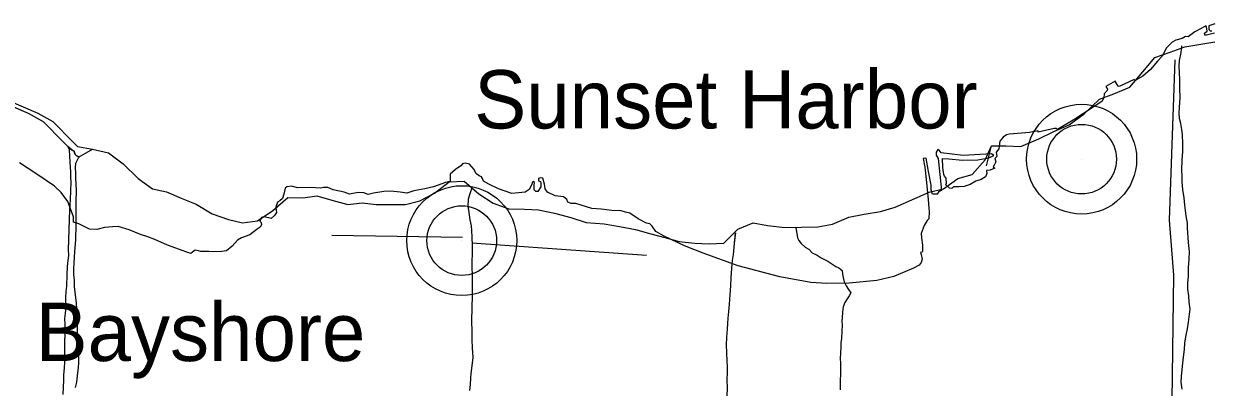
# Model space of a CAD drawing. Extents: x 0 to 34, y 0 to 22.
# Drawn here: x 3.462 to 4.264, y 15.022 to 15.268 of the extents above; entities that cross this region are included whole.
import ezdxf

# ---------------------------------------------------------------- set-up
doc = ezdxf.new("R2010")
doc.units = 0
for name, color, linetype in [('GM_X_Corporation', 7, 'Continuous'), ('GM_X_Major_Lake', 7, 'Continuous'), ('GM_X_Minor_River', 7, 'Continuous'), ('GM_X_Township_Road', 7, 'Continuous'), ('GM_X_Unincorporated', 7, 'Continuous'), ('GM_X_Unincorporated_Location', 7, 'Continuous'), ('GM_X_Unincorporated_Text', 7, 'Continuous')]:
    doc.layers.add(name, color=color, linetype=linetype)

msp = doc.modelspace()

# ---------------------------------------------------------------- linework, layer by layer
at = {"layer": 'GM_X_Corporation'}
for points in [[(4.26677, 15.262), (4.26154, 15.26063), (4.26034, 15.26054), (4.26, 15.262), (4.26197, 15.2632), (4.26154, 15.2662), (4.26103, 15.2668), (4.25794, 15.26517), (4.25366, 15.26294), (4.24903, 15.25951), (4.24723, 15.25977), (4.24492, 15.25831), (4.24063, 15.2572), (4.23831, 15.25574), (4.23437, 15.25206), (4.23137, 15.24631), (4.22829, 15.24305), (4.22357, 15.2374), (4.21832, 15.23276), (4.21316, 15.22976), (4.2126, 15.23046), (4.20246, 15.22589), (4.20163, 15.22608), (4.19974, 15.22943), (4.1934, 15.22583), (4.1946, 15.22394), (4.19434, 15.22308), (4.1922, 15.22094), (4.19203, 15.21803), (4.19057, 15.21571), (4.17232, 15.20371), (4.16075, 15.19677), (4.16006, 15.19728), (4.15852, 15.19746), (4.15346, 15.19617), (4.14754, 15.19497), (4.14763, 15.19574), (4.14172, 15.19463), (4.12817, 15.19343), (4.12612, 15.19317), (4.12397, 15.19146), (4.12166, 15.18871), (4.12098, 15.18357), (4.11926, 15.18134), (4.11977, 15.17843), (4.1184, 15.17697), (4.119, 15.17474), (4.11814, 15.17303), (4.11712, 15.1714), (4.11823, 15.17046), (4.11506, 15.16917), (4.11275, 15.16883), (4.113, 15.16686), (4.11189, 15.16463), (4.10915, 15.16283), (4.10546, 15.16171), (4.10169, 15.15949), (4.09766, 15.15803), (4.09423, 15.15786), (4.09038, 15.15786), (4.08917, 15.15674), (4.08755, 15.15691), (4.08515, 15.15914), (4.08558, 15.16026), (4.0854, 15.16368), (4.08437, 15.16514), (4.08377, 15.16626), (4.08309, 15.17106), (4.08283, 15.17697), (4.0872, 15.17688), (4.09637, 15.17586), (4.10675, 15.1762), (4.1142, 15.17757), (4.11763, 15.17903), (4.116, 15.18014), (4.09689, 15.17911), (4.08197, 15.18083), (4.08069, 15.18263), (4.07975, 15.18314), (4.07854, 15.18134), (4.07854, 15.17937), (4.07992, 15.17714), (4.08215, 15.15546), (4.08052, 15.15477), (4.07923, 15.15288), (4.07606, 15.1528), (4.07529, 15.15571), (4.0752, 15.15889), (4.0734, 15.16823), (4.07177, 15.17731), (4.06989, 15.17706), (4.071, 15.17123), (4.07203, 15.16086), (4.07315, 15.14929), (4.07357, 15.14337), (4.07383, 15.14106), (4.07357, 15.13617), (4.07263, 15.13514), (4.07058, 15.13163), (4.06843, 15.12623), (4.06869, 15.12323), (4.06938, 15.11834), (4.06929, 15.11406), (4.06886, 15.11354), (4.068, 15.11337), (4.0686, 15.11209), (4.06912, 15.10883), (4.06843, 15.10651), (4.06715, 15.1048), (4.06329, 15.10283), (4.04992, 15.09717), (4.0386, 15.09452), (4.01975, 15.09254), (4.00466, 15.09229), (3.99378, 15.09306), (3.97286, 15.09691), (3.94466, 15.10429), (3.92109, 15.11303), (3.9085, 15.1178), (3.90421, 15.11989), (3.89461, 15.12434), (3.88895, 15.1276), (3.88655, 15.13129), (3.88492, 15.13283), (3.88278, 15.13326), (3.87703, 15.13617), (3.87155, 15.13994), (3.86864, 15.14063), (3.86555, 15.14166), (3.85929, 15.14183), (3.85218, 15.14268), (3.84575, 15.14311), (3.83487, 15.14646), (3.83178, 15.14646), (3.82964, 15.14757), (3.82895, 15.14929), (3.82664, 15.15109), (3.82089, 15.15177), (3.81575, 15.15417), (3.81429, 15.1564), (3.81387, 15.15974), (3.81258, 15.16377), (3.81112, 15.16403), (3.80975, 15.16343), (3.80967, 15.16188), (3.81112, 15.16154), (3.81138, 15.16034), (3.81129, 15.15777), (3.80924, 15.15469), (3.80795, 15.15469), (3.80675, 15.15571), (3.80675, 15.15889), (3.80692, 15.16086), (3.80615, 15.16137), (3.80564, 15.16103), (3.80495, 15.15889), (3.80341, 15.15614), (3.80066, 15.15417), (3.79166, 15.15331), (3.78258, 15.15657), (3.77606, 15.15966), (3.77255, 15.1618), (3.77195, 15.16343), (3.77109, 15.16454), (3.76998, 15.16506), (3.76758, 15.16668), (3.76629, 15.16969), (3.76304, 15.17311), (3.76021, 15.1738), (3.75824, 15.17346), (3.75712, 15.172), (3.75361, 15.1696), (3.75172, 15.16806), (3.75001, 15.16643), (3.74992, 15.16326), (3.75001, 15.16154), (3.74692, 15.16069), (3.7387, 15.15777), (3.73278, 15.15657), (3.72532, 15.15512), (3.72078, 15.15348), (3.71624, 15.15426), (3.70981, 15.15494), (3.70518, 15.15477), (3.69815, 15.15366), (3.69447, 15.15271), (3.69164, 15.15374), (3.68787, 15.15409), (3.68195, 15.1528), (3.67835, 15.15426), (3.67089, 15.15589), (3.66729, 15.15734), (3.66438, 15.15751), (3.66249, 15.15691), (3.6553, 15.15743), (3.64681, 15.15717), (3.64287, 15.15837), (3.63944, 15.15794), (3.63833, 15.15691), (3.63755, 15.1528), (3.63669, 15.14997), (3.63481, 15.14843), (3.6331, 15.1474), (3.63198, 15.14414), (3.6325, 15.14046), (3.63112, 15.1384), (3.62896, 15.1363), (3.6241, 15.13746), (3.62247, 15.13711), (3.62124, 15.13468), (3.62221, 15.1336), (3.62247, 15.13223), (3.62144, 15.13052), (3.61955, 15.12914), (3.61441, 15.12529), (3.60875, 15.12331), (3.60618, 15.12177), (3.6025, 15.11757), (3.59873, 15.11457), (3.59564, 15.11397), (3.58981, 15.11389), (3.58681, 15.11414), (3.58132, 15.11414), (3.57987, 15.11457), (3.57747, 15.11492), (3.57567, 15.11371), (3.57455, 15.11277), (3.57198, 15.11354), (3.55878, 15.11843), (3.5503, 15.12228), (3.54541, 15.12409), (3.54061, 15.12554), (3.53281, 15.12871), (3.52544, 15.13103), (3.52158, 15.13086), (3.51627, 15.13026), (3.51095, 15.12897), (3.50615, 15.12914), (3.49878, 15.13274), (3.49527, 15.13386), (3.49518, 15.13754), (3.49133, 15.148), (3.48695, 15.154), (3.48233, 15.15828), (3.47041, 15.16634), (3.45867, 15.17414)], [(4.26677, 15.262), (4.26154, 15.26063), (4.26034, 15.26054), (4.26, 15.262), (4.26197, 15.2632), (4.26154, 15.2662), (4.26103, 15.2668), (4.25794, 15.26517), (4.25366, 15.26294), (4.24903, 15.25951), (4.24723, 15.25977), (4.24492, 15.25831), (4.24063, 15.2572), (4.23831, 15.25574), (4.23437, 15.25206), (4.23137, 15.24631), (4.22829, 15.24305), (4.22357, 15.2374), (4.21832, 15.23276), (4.21316, 15.22976), (4.2126, 15.23046), (4.20246, 15.22589), (4.20163, 15.22608), (4.19974, 15.22943), (4.1934, 15.22583), (4.1946, 15.22394), (4.19434, 15.22308), (4.1922, 15.22094), (4.19203, 15.21803), (4.19057, 15.21571), (4.17232, 15.20371), (4.16075, 15.19677), (4.16006, 15.19728), (4.15852, 15.19746), (4.15346, 15.19617), (4.14754, 15.19497), (4.14763, 15.19574), (4.14172, 15.19463), (4.12817, 15.19343), (4.12612, 15.19317), (4.12397, 15.19146), (4.12166, 15.18871), (4.12098, 15.18357), (4.11926, 15.18134), (4.11977, 15.17843), (4.1184, 15.17697), (4.119, 15.17474), (4.11814, 15.17303), (4.11712, 15.1714), (4.11823, 15.17046), (4.11506, 15.16917), (4.11275, 15.16883), (4.113, 15.16686), (4.11189, 15.16463), (4.10915, 15.16283), (4.10546, 15.16171), (4.10169, 15.15949), (4.09766, 15.15803), (4.09423, 15.15786), (4.09038, 15.15786), (4.08917, 15.15674), (4.08755, 15.15691), (4.08515, 15.15914), (4.08558, 15.16026), (4.0854, 15.16368), (4.08437, 15.16514), (4.08377, 15.16626), (4.08309, 15.17106), (4.08283, 15.17697), (4.0872, 15.17688), (4.09637, 15.17586), (4.10675, 15.1762), (4.1142, 15.17757), (4.11763, 15.17903), (4.116, 15.18014), (4.09689, 15.17911), (4.08197, 15.18083), (4.08069, 15.18263), (4.07975, 15.18314), (4.07854, 15.18134), (4.07854, 15.17937), (4.07992, 15.17714), (4.08215, 15.15546), (4.08052, 15.15477), (4.07923, 15.15288), (4.07606, 15.1528), (4.07529, 15.15571), (4.0752, 15.15889), (4.0734, 15.16823), (4.07177, 15.17731), (4.06989, 15.17706), (4.071, 15.17123), (4.07203, 15.16086), (4.07315, 15.14929), (4.07357, 15.14337), (4.07383, 15.14106), (4.07357, 15.13617), (4.07263, 15.13514), (4.07058, 15.13163), (4.06843, 15.12623), (4.06869, 15.12323), (4.06938, 15.11834), (4.06929, 15.11406), (4.06886, 15.11354), (4.068, 15.11337), (4.0686, 15.11209), (4.06912, 15.10883), (4.06843, 15.10651), (4.06715, 15.1048), (4.06329, 15.10283), (4.04992, 15.09717), (4.0386, 15.09452), (4.01975, 15.09254), (4.00466, 15.09229), (3.99378, 15.09306), (3.97286, 15.09691), (3.94466, 15.10429), (3.92109, 15.11303), (3.9085, 15.1178), (3.90421, 15.11989), (3.89461, 15.12434), (3.88895, 15.1276), (3.88655, 15.13129), (3.88492, 15.13283), (3.88278, 15.13326), (3.87703, 15.13617), (3.87155, 15.13994), (3.86864, 15.14063), (3.86555, 15.14166), (3.85929, 15.14183), (3.85218, 15.14268), (3.84575, 15.14311), (3.83487, 15.14646), (3.83178, 15.14646), (3.82964, 15.14757), (3.82895, 15.14929), (3.82664, 15.15109), (3.82089, 15.15177), (3.81575, 15.15417), (3.81429, 15.1564), (3.81387, 15.15974), (3.81258, 15.16377), (3.81112, 15.16403), (3.80975, 15.16343), (3.80967, 15.16188), (3.81112, 15.16154), (3.81138, 15.16034), (3.81129, 15.15777), (3.80924, 15.15469), (3.80795, 15.15469), (3.80675, 15.15571), (3.80675, 15.15889), (3.80692, 15.16086), (3.80615, 15.16137), (3.80564, 15.16103), (3.80495, 15.15889), (3.80341, 15.15614), (3.80066, 15.15417), (3.79166, 15.15331), (3.78258, 15.15657), (3.77606, 15.15966), (3.77255, 15.1618), (3.77195, 15.16343), (3.77109, 15.16454), (3.76998, 15.16506), (3.76758, 15.16668), (3.76629, 15.16969), (3.76304, 15.17311), (3.76021, 15.1738), (3.75824, 15.17346), (3.75712, 15.172), (3.75361, 15.1696), (3.75172, 15.16806), (3.75001, 15.16643), (3.74992, 15.16326), (3.75001, 15.16154), (3.74692, 15.16069), (3.7387, 15.15777), (3.73278, 15.15657), (3.72532, 15.15512), (3.72078, 15.15348), (3.71624, 15.15426), (3.70981, 15.15494), (3.70518, 15.15477), (3.69815, 15.15366), (3.69447, 15.15271), (3.69164, 15.15374), (3.68787, 15.15409), (3.68195, 15.1528), (3.67835, 15.15426), (3.67089, 15.15589), (3.66729, 15.15734), (3.66438, 15.15751), (3.66249, 15.15691), (3.6553, 15.15743), (3.64681, 15.15717), (3.64287, 15.15837), (3.63944, 15.15794), (3.63833, 15.15691), (3.63755, 15.1528), (3.63669, 15.14997), (3.63481, 15.14843), (3.6331, 15.1474), (3.63198, 15.14414), (3.6325, 15.14046), (3.63112, 15.1384), (3.62896, 15.1363), (3.6241, 15.13746), (3.62247, 15.13711), (3.62124, 15.13468), (3.62221, 15.1336), (3.62247, 15.13223), (3.62144, 15.13052), (3.61955, 15.12914), (3.61441, 15.12529), (3.60875, 15.12331), (3.60618, 15.12177), (3.6025, 15.11757), (3.59873, 15.11457), (3.59564, 15.11397), (3.58981, 15.11389), (3.58681, 15.11414), (3.58132, 15.11414), (3.57987, 15.11457), (3.57747, 15.11492), (3.57567, 15.11371), (3.57455, 15.11277), (3.57198, 15.11354), (3.55878, 15.11843), (3.5503, 15.12228), (3.54541, 15.12409), (3.54061, 15.12554), (3.53281, 15.12871), (3.52544, 15.13103), (3.52158, 15.13086), (3.51627, 15.13026), (3.51095, 15.12897), (3.50615, 15.12914), (3.49878, 15.13274), (3.49527, 15.13386), (3.49518, 15.13754), (3.49133, 15.148), (3.48695, 15.154), (3.48233, 15.15828), (3.47041, 15.16634), (3.45867, 15.17414)], [(4.2672, 15.26834), (4.26309, 15.26688), (4.263, 15.26448), (4.26386, 15.26354), (4.26497, 15.26354)], [(4.2672, 15.26834), (4.26309, 15.26688), (4.263, 15.26448), (4.26386, 15.26354), (4.26497, 15.26354)]]:
    msp.add_lwpolyline(points, dxfattribs=at)
at = {"layer": 'GM_X_Major_Lake'}
for points in [[(3.36062, 15.25814), (3.37105, 15.25226), (3.38109, 15.25036), (3.39209, 15.24599), (3.40308, 15.24011), (3.41294, 15.23441), (3.42412, 15.22967), (3.4353, 15.22245), (3.44478, 15.21638), (3.45464, 15.21201), (3.46468, 15.20784), (3.47473, 15.20214), (3.48857, 15.18809), (3.49141, 15.18516)], [(3.36714, 15.25814), (3.37756, 15.25226), (3.38761, 15.25036), (3.3986, 15.24599), (3.40959, 15.24011), (3.41945, 15.23441), (3.43063, 15.22967), (3.44181, 15.22245), (3.45129, 15.21638), (3.46115, 15.21201), (3.47119, 15.20784), (3.48124, 15.20214), (3.49508, 15.18809), (3.49792, 15.18516)], [(3.49792, 15.18516), (3.50809, 15.18335), (3.51889, 15.18088), (3.52894, 15.17348), (3.53898, 15.16341), (3.54865, 15.15658), (3.55813, 15.15449), (3.56817, 15.15013), (3.57822, 15.14614), (3.58902, 15.13968), (3.60002, 15.1357), (3.60949, 15.13342), (3.61973, 15.13494), (3.62996, 15.14178), (3.64019, 15.15071), (3.65024, 15.15033), (3.6599, 15.15185), (3.66995, 15.14881), (3.68075, 15.14578), (3.69042, 15.14692), (3.69989, 15.14578), (3.71032, 15.14578), (3.71979, 15.14597), (3.72946, 15.14844), (3.73931, 15.15357), (3.74935, 15.16117), (3.7594, 15.16174), (3.76945, 15.15301), (3.77911, 15.14674), (3.78973, 15.14295), (3.80015, 15.14276), (3.80963, 15.14219), (3.82043, 15.13991), (3.83161, 15.13706), (3.84204, 15.13365), (3.85417, 15.13289), (3.86459, 15.13099), (3.8752, 15.12891), (3.88563, 15.12606), (3.8951, 15.12359), (3.90477, 15.12093), (3.9152, 15.1198), (3.92505, 15.11923), (3.93509, 15.11961), (3.94457, 15.12929), (3.9548, 15.13347), (3.96466, 15.13158), (3.9766, 15.13025), (3.98759, 15.13044), (3.99858, 15.13082), (4.00863, 15.13253), (4.01962, 15.13728), (4.03004, 15.13937), (4.04104, 15.14108), (4.05089, 15.14412), (4.06416, 15.15001), (4.07382, 15.15419), (4.08349, 15.15647), (4.09334, 15.1635), (4.10301, 15.16616), (4.11172, 15.17603), (4.11608, 15.18553), (4.12575, 15.18572), (4.13579, 15.18515), (4.14811, 15.19047), (4.15815, 15.19541), (4.16858, 15.19978), (4.17881, 15.20737), (4.18904, 15.21725), (4.1989, 15.22086), (4.2097, 15.22542), (4.21842, 15.23568), (4.22656, 15.24555), (4.2368, 15.24916), (4.24684, 15.25277), (4.25632, 15.25429), (4.26712, 15.256)], [(3.49912, 15.17818), (3.50809, 15.18335), (3.51889, 15.18088), (3.52894, 15.17348), (3.53898, 15.16341), (3.54865, 15.15658), (3.55813, 15.15449), (3.56817, 15.15013), (3.57822, 15.14614), (3.58902, 15.13968), (3.60002, 15.1357), (3.60949, 15.13342), (3.61973, 15.13494), (3.62996, 15.14178), (3.64019, 15.15071), (3.65024, 15.15033), (3.6599, 15.15185), (3.66995, 15.14881), (3.68075, 15.14578), (3.69042, 15.14692), (3.69989, 15.14578), (3.71032, 15.14578), (3.71979, 15.14597), (3.72946, 15.14844), (3.73931, 15.15357), (3.74935, 15.16117), (3.7594, 15.16174), (3.76945, 15.15301), (3.77911, 15.14674), (3.78973, 15.14295), (3.80015, 15.14276), (3.80963, 15.14219), (3.82043, 15.13991), (3.83161, 15.13706), (3.84204, 15.13365), (3.85417, 15.13289), (3.86459, 15.13099), (3.8752, 15.12891), (3.88563, 15.12606), (3.8951, 15.12359), (3.90477, 15.12093), (3.9152, 15.1198), (3.92505, 15.11923), (3.93509, 15.11961), (3.94457, 15.12929), (3.9548, 15.13347), (3.96466, 15.13158), (3.9766, 15.13025), (3.98759, 15.13044), (3.99858, 15.13082), (4.00863, 15.13253), (4.01962, 15.13728), (4.03004, 15.13937), (4.04104, 15.14108), (4.05089, 15.14412), (4.06416, 15.15001), (4.07382, 15.15419), (4.08349, 15.15647), (4.09334, 15.1635), (4.10301, 15.16616), (4.11172, 15.17603), (4.11608, 15.18553), (4.12575, 15.18572), (4.13579, 15.18515), (4.14811, 15.19047), (4.15815, 15.19541), (4.16858, 15.19978), (4.17881, 15.20737), (4.18904, 15.21725), (4.1989, 15.22086), (4.2097, 15.22542), (4.21842, 15.23568), (4.22656, 15.24555), (4.2368, 15.24916), (4.24684, 15.25277), (4.25632, 15.25429), (4.26712, 15.256)], [(4.11275, 15.17205), (4.11608, 15.18553), (4.12575, 15.18572), (4.13579, 15.18515), (4.14811, 15.19047), (4.15815, 15.19541), (4.16858, 15.19978), (4.17881, 15.20737), (4.18904, 15.21725), (4.1989, 15.22086), (4.2097, 15.22542), (4.21842, 15.23568), (4.22656, 15.24555), (4.2368, 15.24916), (4.24684, 15.25277), (4.25632, 15.25429), (4.26712, 15.256)], [(3.49141, 15.18516), (3.4944, 15.18276), (3.49567, 15.18195), (3.49594, 15.18087), (3.49642, 15.17973), (3.49701, 15.17917), (3.49787, 15.17861), (3.49912, 15.17818)]]:
    msp.add_lwpolyline(points, dxfattribs=at)
at = {"layer": 'GM_X_Minor_River'}
for p in [(3.76464, 15.11999), (3.88273, 15.11166)]:
    msp.add_line(p, (3.88273, 15.11166), dxfattribs=at)
for points in [[(4.24495, 15.02071), (4.24433, 15.02567), (4.24444, 15.02946), (4.24521, 15.03647), (4.2457, 15.04045), (4.24667, 15.04783), (4.24679, 15.052), (4.24748, 15.05616), (4.24858, 15.06164), (4.24928, 15.06618), (4.25001, 15.07167), (4.2503, 15.07508), (4.24967, 15.07985), (4.24941, 15.08403), (4.24878, 15.08861), (4.2489, 15.09279), (4.24922, 15.09715), (4.24939, 15.10322), (4.24973, 15.10872), (4.24989, 15.11404), (4.2493, 15.12013), (4.24863, 15.13003), (4.24854, 15.13326), (4.24773, 15.13823), (4.2468, 15.14547), (4.24637, 15.15043), (4.24539, 15.15615), (4.24497, 15.16129), (4.24489, 15.16529), (4.24481, 15.16909), (4.24501, 15.17611), (4.24536, 15.1818), (4.24551, 15.18693), (4.24512, 15.19321), (4.24484, 15.19663), (4.2442, 15.20083), (4.24315, 15.20409), (4.24308, 15.20808), (4.24317, 15.2115), (4.24355, 15.21814), (4.24336, 15.22479), (4.24333, 15.2303), (4.24309, 15.23525), (4.24303, 15.23962), (4.24313, 15.24342), (4.24424, 15.2489), (4.24475, 15.25344)], [(3.49141, 15.18516), (3.4923, 15.18322), (3.49255, 15.17866), (3.49282, 15.17466), (3.49291, 15.17124), (3.4932, 15.168), (3.49329, 15.16439), (3.49338, 15.16097), (3.49304, 15.1492), (3.49275, 15.1456), (3.49246, 15.14218), (3.4917, 15.11542), (3.49178, 15.11143), (3.49149, 15.10802), (3.49099, 15.10385), (3.49064, 15.09835), (3.49042, 15.09057), (3.49013, 15.08697), (3.48982, 15.0828), (3.48991, 15.07937), (3.49001, 15.07614), (3.48952, 15.07236), (3.48923, 15.06857), (3.4893, 15.06457), (3.48957, 15.06077), (3.48947, 15.05716), (3.48918, 15.05375), (3.48909, 15.05033), (3.48916, 15.04615), (3.48925, 15.04273), (3.48914, 15.03893), (3.48885, 15.03533), (3.48852, 15.0304), (3.48842, 15.02698), (3.48814, 15.0173)], [(3.49912, 15.17818), (3.49787, 15.17861), (3.49701, 15.17917), (3.49642, 15.17973), (3.49594, 15.18087), (3.49567, 15.18195), (3.4944, 15.18276), (3.49141, 15.18516)], [(3.49663, 15.022), (3.49749, 15.02558), (3.49799, 15.02975), (3.49853, 15.03543), (3.49882, 15.03865), (3.49877, 15.04378), (3.49852, 15.04835), (3.49842, 15.05158), (3.49814, 15.05482), (3.49789, 15.05958), (3.49799, 15.06299), (3.49773, 15.06718), (3.49769, 15.07231), (3.4974, 15.07555), (3.49731, 15.07916), (3.49685, 15.08297), (3.49637, 15.08622), (3.49592, 15.09041), (3.49585, 15.09459), (3.49558, 15.0984), (3.49551, 15.10258), (3.49561, 15.106), (3.49592, 15.11017), (3.49621, 15.11377), (3.49683, 15.12211), (3.49711, 15.13198), (3.49704, 15.13616), (3.49714, 15.13996), (3.49705, 15.14338), (3.49697, 15.14699), (3.49722, 15.15592), (3.49712, 15.15915), (3.49688, 15.1639), (3.49679, 15.16733), (3.49669, 15.17075), (3.49679, 15.17398), (3.49852, 15.17757), (3.49912, 15.17818)], [(3.76469, 15.157), (3.7635, 15.15374), (3.76225, 15.14959), (3.76192, 15.14466), (3.76256, 15.14047), (3.76336, 15.1355), (3.7642, 15.13149), (3.76448, 15.12825), (3.76473, 15.12369), (3.76477, 15.11818), (3.76479, 15.1121), (3.76466, 15.10792), (3.76471, 15.10298), (3.76477, 15.09842), (3.76492, 15.09005), (3.76495, 15.08454), (3.76445, 15.06708), (3.76462, 15.05967), (3.76466, 15.05434), (3.76488, 15.04883), (3.76526, 15.04236), (3.76472, 15.03668), (3.764, 15.03138), (3.76372, 15.02816), (3.76341, 15.02398), (3.76311, 15.02)], [(3.93704, 15.00795), (3.93746, 15.02257), (3.93737, 15.02618), (3.93756, 15.03301), (3.93747, 15.03624), (3.93738, 15.03986), (3.93697, 15.04557), (3.93693, 15.0507), (3.93708, 15.05601), (3.93743, 15.06151), (3.93772, 15.0653), (3.93802, 15.0689), (3.93834, 15.07345), (3.93886, 15.07838), (3.93942, 15.08482), (3.93978, 15.0907), (3.93993, 15.09621), (3.9405, 15.10284), (3.94084, 15.10796), (3.94153, 15.11212), (3.94291, 15.1267), (3.94213, 15.12008)], [(3.98382, 15.13037), (3.98486, 15.1233), (3.98582, 15.12141), (3.98735, 15.11952), (3.99002, 15.11706), (3.99249, 15.11555), (3.99479, 15.11309), (3.99821, 15.11158), (4.00088, 15.10969), (4.00544, 15.10762), (4.00735, 15.10611), (4.01077, 15.10384), (4.01287, 15.1029), (4.01515, 15.1012), (4.01535, 15.09873), (4.01575, 15.09646), (4.01652, 15.09361), (4.01786, 15.09077), (4.01939, 15.0883), (4.02092, 15.08603), (4.01979, 15.08413), (4.01848, 15.08203), (4.01678, 15.07956), (4.01585, 15.07652), (4.01529, 15.07291), (4.01512, 15.06911), (4.01495, 15.06702), (4.01496, 15.06398), (4.01479, 15.06037), (4.01463, 15.05486), (4.01426, 15.05239), (4.01428, 15.04916), (4.01392, 15.04536), (4.01375, 15.04137), (4.01395, 15.03871), (4.01398, 15.03207), (4.01382, 15.0258), (4.01366, 15.02029)]]:
    msp.add_lwpolyline(points, dxfattribs=at)
at = {"layer": 'GM_X_Township_Road'}
msp.add_line((3.66992, 15.12517), (3.75837, 15.12373), dxfattribs=at)
msp.add_lwpolyline([(4.23844, 14.75509), (4.23792, 14.99632), (4.23943, 15.09808), (4.23634, 15.1352), (4.24019, 15.24378)], dxfattribs=at)
at = {"layer": 'GM_X_Unincorporated'}
for centre, radius in [((4.17702, 15.1766), 0.0372), ((4.17702, 15.1766), 0.02358), ((3.75781, 15.12142), 0.0372), ((3.75781, 15.12142), 0.02358)]:
    msp.add_circle(centre, radius, dxfattribs=at)
at = {"layer": 'GM_X_Unincorporated_Location'}
for p, q in [((4.17702, 15.1766), (4.17702, 15.1766)), ((3.75781, 15.12142), (3.75781, 15.12142))]:
    msp.add_line(p, q, dxfattribs=at)

# ---------------------------------------------------------------- texts
at = {"layer": 'GM_X_Unincorporated_Text'}
for s, height, p in [('Sunset Harbor', 0.0394886, (3.76621, 15.19737)), ('Bayshore', 0.039489, (3.46954, 15.03988))]:
    msp.add_text(s, height=height, rotation=0.00001, dxfattribs=at).set_placement(p)

doc.saveas('drawing.dxf')
